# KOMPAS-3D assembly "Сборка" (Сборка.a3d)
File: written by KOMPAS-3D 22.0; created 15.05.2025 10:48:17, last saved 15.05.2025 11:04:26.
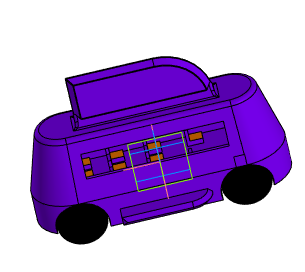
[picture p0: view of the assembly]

Document properties: Автор: Пользователь Windows; Полное имя файла: C:\Users\Student\Desktop\Сборка.a3d

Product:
- Component [detail]: Деталь  | qty 1  | Масса: 3.41749; source file: низ корпуса.m3d
- Component [detail]: Деталь  | qty 1  | Масса: 2.164064; source file: верх корпуса.m3d
- Component [detail]: Деталь  | qty 2  | Масса: 0.134307; source file: калисо дырка.m3d
- Component [detail]: Деталь  | qty 2  | Масса: 0.135759; source file: калисо палка.m3d
- Part/product: Сборка
    Масса: 6.121686

Referenced files in C:\Users\Student\Desktop\: низ корпуса.m3d, верх корпуса.m3d, калисо дырка.m3d, калисо палка.m3d
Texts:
  Деталь (1)
  Деталь (2)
